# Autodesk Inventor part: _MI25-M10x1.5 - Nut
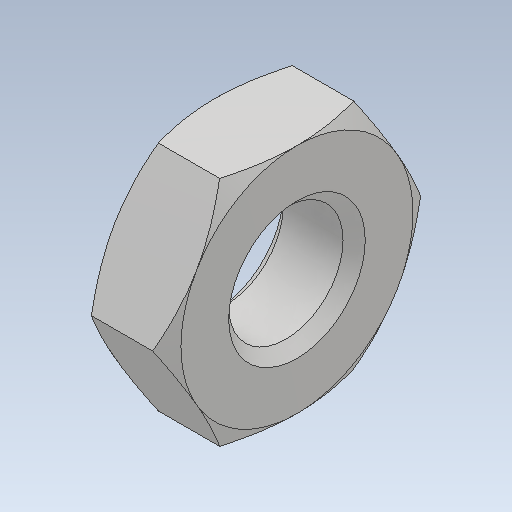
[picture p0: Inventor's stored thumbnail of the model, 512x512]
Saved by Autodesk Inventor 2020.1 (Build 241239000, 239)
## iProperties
Created: 2020-04
Part Number: _MI25-M10x1.5 - Nut
Material: Generic
Document SubType Name: Modeling
Designer: Safarabadi
Density: 1 g/cm^3
Appearance: Default
Author: Safarabadi
Revision Number: NONE
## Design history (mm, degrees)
feature "_MI25-M10x1.5 - Nut"
body "Solid1"
